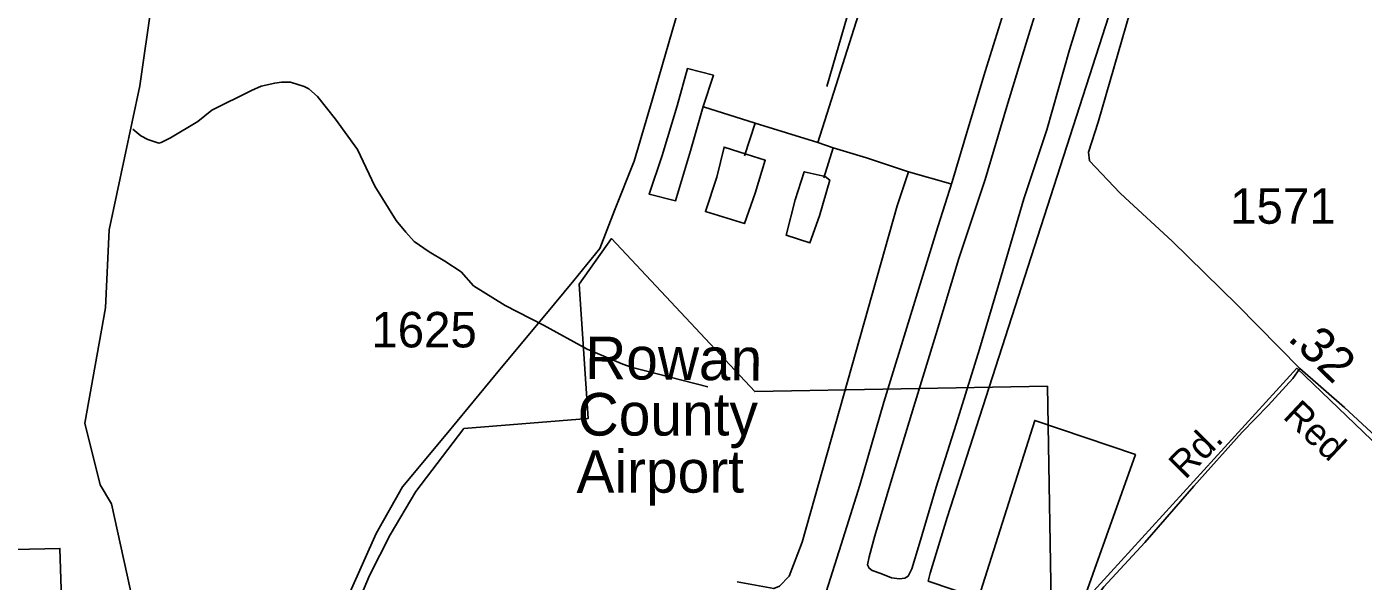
# Model space of a CAD drawing. Extents: x 1473865 to 1648260, y 639067 to 773536.
# Drawn here: x 1545209 to 1549921, y 692603 to 694557 of the extents above; entities that cross this region are included whole.
import ezdxf

# ---------------------------------------------------------------- set-up
doc = ezdxf.new("R2010")
doc.units = 0
for name, color, linetype in [('Exist Aviation Commercial or Municipal Label', 7, 'Continuous'), ('Exist Aviation Commercial or Municipal Perimeter Paved', 7, 'Continuous'), ('Exist Boundary Political City Limit New', 7, 'Continuous'), ('Exist Hydrographic Creek Single Shore', 7, 'Continuous'), ('Exist Hydrographic Misc Water Feature', 7, 'Continuous'), ('Exist Road Non-System Type 51', 7, 'Continuous'), ('Exist Road Non-System Type 51 Label', 7, 'Continuous'), ('Exist Road Secondary Mileage Hundredths English Label', 7, 'Continuous'), ('Exist Road Secondary Type 51 Attributed', 7, 'Continuous'), ('Exist Road Secondary Type 51 Label', 7, 'Continuous'), ('Exist Road Secondary Type 51 Number Label', 7, 'Continuous'), ('Map Preparation Boundary City Limit Buffer Line', 7, 'Continuous')]:
    doc.layers.add(name, color=color, linetype=linetype)

msp = doc.modelspace()

# ---------------------------------------------------------------- linework, layer by layer
at = {"layer": 'Exist Aviation Commercial or Municipal Perimeter Paved'}
for points in [[(1549286.7, 695409), (1548454.1, 692828.4), (1548394.9, 692631.3), (1548387.4, 692604)], [(1548179.8, 692689.1), (1548199.1, 692762.9), (1548262.6, 692975.9), (1548336.8, 693218.8), (1548414.9, 693471.5), (1548495.6, 693740.4), (1548588.3, 694018.9), (1548664.7, 694275.9), (1548732.4, 694498.8), (1548776.7, 694640.2)], [(1547776.4, 690720.4), (1547595.9, 690798.6), (1547511.6, 690485.6), (1547415.4, 690533.8), (1547535.9, 690919), (1547561.2, 691000.7), (1547603.8, 691148.1), (1547680, 691402.9), (1547747.9, 691623.8), (1547821.9, 691872.7), (1547902.5, 692137.6), (1547959.6, 692320.7), (1548012.8, 692517.9), (1548080.4, 692732.9), (1548146.1, 692941.9), (1548231, 693234.7), (1548421.4, 693851.8), (1548472, 694011), (1548527.2, 694196.2), (1548588.7, 694399.3), (1548658.5, 694624.2)], [(1548930.4, 694619.5), (1548886, 694476.1), (1548805.3, 694193.4), (1548725.1, 693950.5), (1548644.6, 693677.8), (1548568.2, 693421), (1548485.8, 693156.1), (1548416.1, 692935.2), (1548356.6, 692736.1), (1548329.2, 692646.4), (1548316.7, 692620.7), (1548305.1, 692613.7), (1548286.5, 692611.3), (1548258.5, 692615.6), (1548220.8, 692630.4), (1548190.2, 692641.4), (1548179.2, 692649.3), (1548173.4, 692661.2), (1548179.8, 692689.1)], [(1547594.4, 694276.3), (1547630.2, 694385.8), (1547538.6, 694409.5), (1547502.3, 694277.9), (1547449.4, 694102.7), (1547403.2, 693967.4), (1547496.8, 693943.9), (1547549.8, 694119.1), (1547594.4, 694276.3)], [(1547745.6, 694107.6), (1547667.9, 694132.9), (1547642.2, 694027.4), (1547602.1, 693905.9), (1547739.5, 693863.5), (1547777.3, 693971), (1547813.2, 694086.4), (1547745.6, 694107.6)], [(1548024.4, 694028.7), (1548040.1, 694016.6), (1548004, 693891), (1547970.4, 693795.5), (1547886.7, 693823), (1547918.9, 693946.6), (1547950.5, 694046), (1548024.4, 694028.7)], [(1548387.4, 692604), (1548564.6, 692544.1), (1548763.2, 693170), (1549118.2, 693049.7), (1548817.3, 692207), (1548817.3, 692309.3), (1548781.2, 692309.3), (1548703, 691966.3), (1548697, 691563), (1548666.9, 690997.2), (1548137.4, 691051.4), (1548221.6, 690919), (1548480.4, 690931), (1548456.3, 690822.7), (1548221.6, 690852.8), (1548059.2, 691051.4), (1547974.9, 691051.4), (1547872.6, 690720.4), (1548023.1, 690467.6), (1548648.9, 690268.9), (1548588.7, 690112.5), (1547974.9, 690353.2), (1547776.4, 690720.4)]]:
    msp.add_lwpolyline(points, dxfattribs=at)
at = {"layer": 'Exist Boundary Political City Limit New'}
msp.add_lwpolyline([(1550303.1, 692762.7), (1549687.6, 693353.7), (1548922.2, 692515.4), (1548822.9, 692391.2), (1548807.9, 693290), (1547776, 693271.3), (1547271.4, 693810.6), (1547156.9, 693650.1), (1547188.5, 693176.6), (1546750.5, 693141.1), (1546581.2, 692919.3), (1546490, 692766.8), (1546417.6, 692623.3), (1546344.5, 692451.1), (1546292.9, 692292.6), (1546220.5, 691956), (1546205.5, 691700.6), (1545361.1, 691645.4), (1545326, 692719.1), (1544737.1, 692705.2)], dxfattribs=at)
at = {"layer": 'Exist Hydrographic Creek Single Shore'}
msp.add_lwpolyline([(1546704.6, 689412.2), (1546715.6, 690114.4), (1546602.6, 690339.9), (1546492.6, 690726.2), (1546402.5, 690869.1), (1546287.6, 690986.3), (1546191.5, 691214.8), (1546143.6, 691356.9), (1545914.6, 691666.8), (1545778.6, 691978.1), (1545699.6, 692304.7), (1545594.5, 692480.7), (1545508.6, 692876.4), (1545468.6, 692942.9), (1545413.6, 693160.6), (1545486.6, 693566.1), (1545499.6, 693841.7), (1545607.6, 694348.2), (1545691.6, 694930.8)], dxfattribs=at)
at = {"layer": 'Exist Hydrographic Misc Water Feature'}
msp.add_lwpolyline([(1545582.7, 694195.5), (1545611.9, 694172.1), (1545635.6, 694159.6), (1545675.4, 694146.8), (1545683.4, 694148.7), (1545715.8, 694166), (1545812, 694223.4), (1545861.7, 694263), (1546001.1, 694332.1), (1546035.4, 694347.4), (1546083.6, 694358.4), (1546107.7, 694362), (1546139.7, 694361.3), (1546187.3, 694346.3), (1546203.2, 694338), (1546234.7, 694311.4), (1546297.8, 694231), (1546375.1, 694124.6), (1546436.6, 693995.4), (1546512.2, 693874), (1546545.5, 693833.3), (1546574.9, 693800.7), (1546628.2, 693763.7), (1546683.6, 693730.6), (1546740.4, 693693.1), (1546783.8, 693644.5), (1546896.5, 693574.3), (1547031.2, 693505.6), (1547185.6, 693420.5), (1547310.6, 693368), (1547340.5, 693357.4), (1547611.1, 693287.9)], dxfattribs=at)
at = {"layer": 'Exist Road Non-System Type 51'}
for p, q in [((1547777.1, 694217.2), (1547595.5, 694275.1)), ((1547777.1, 694217.2), (1547739.9, 694101.5)), ((1547998.4, 694148.9), (1547777.1, 694217.2)), ((1548052.2, 694130.2), (1547998.4, 694148.9)), ((1548052.2, 694130.2), (1548019.1, 694024.6)), ((1548466.9, 694003.9), (1548317.5, 694045.6))]:
    msp.add_line(p, q, dxfattribs=at)
for points in [[(1548401.8, 695121.2), (1548363.8, 695119.6), (1548309.4, 695080.1), (1548262.5, 694998.6), (1548249.8, 694955.3), (1548208.7, 694815), (1548142.2, 694600.6), (1547998.4, 694148.9)], [(1549082.4, 693953.6), (1549062.7, 693971.7), (1548955.8, 694084.9), (1548952.2, 694115), (1548987.1, 694220.8), (1549169.2, 694851.2), (1549165.4, 694873.3), (1549131.7, 694899.6), (1548994.2, 694945), (1548655, 695046.5), (1548555.5, 695081.5)], [(1548317.5, 694045.6), (1548169.8, 694095), (1548052.2, 694130.2)], [(1547713.4, 692600.8), (1547843.2, 692577.6), (1547863.1, 692585.4), (1547897.5, 692621.1), (1547942.7, 692740.7), (1548278.2, 693925.9), (1548317.5, 694045.6)], [(1548803.4, 689775.6), (1548797.9, 689954.7), (1548754.5, 691120.6), (1548745.5, 691352.6), (1548746.4, 691949), (1548768.6, 692089.7), (1548795.9, 692221.6), (1548845, 692345.1), (1548918.1, 692470.5), (1549007.3, 692583.5), (1549150.9, 692740.1), (1549323.5, 692937.9), (1549494.4, 693127.9), (1549586.6, 693222.9), (1549673.4, 693317.9), (1549697.8, 693353.1)]]:
    msp.add_lwpolyline(points, dxfattribs=at)
at = {"layer": 'Exist Road Secondary Type 51 Attributed'}
for points in [[(1548205.5, 694950), (1548030.5, 694345.9)], [(1546235.9, 690781.3), (1546240.2, 690902.6), (1546234.8, 690994.9), (1546202.2, 691198.4), (1546165.1, 691530.9), (1546154.9, 691746.2), (1546185.6, 691951.2), (1546226.6, 692135.7), (1546267.5, 692330.5), (1546349.5, 692566.2), (1546441.7, 692771.3), (1546533.8, 692935.3), (1546687.5, 693119.8), (1546882.1, 693355.6), (1547035.7, 693540.1), (1547138.2, 693663.1), (1547230.3, 693775.8), (1547281.6, 693909.1), (1547351.1, 694083.3), (1547414.7, 694298.6), (1547588.8, 694903.4)], [(1549697.8, 693353.1), (1549477, 693577.3), (1549247.2, 693801.7), (1549082.4, 693953.6)], [(1549697.8, 693353.1), (1549855.5, 693215.1), (1549996.3, 693085.6), (1550164.7, 692923.9), (1550570.8, 692519.3), (1550662, 692440.4), (1550681.8, 692412.2), (1550842.3, 692262.5), (1550959.2, 692147.3), (1551207, 691902.6), (1551337.8, 691779.1), (1551459.8, 691676.2)]]:
    msp.add_lwpolyline(points, dxfattribs=at)
at = {"layer": 'Map Preparation Boundary City Limit Buffer Line'}
msp.add_lwpolyline([(1550303.1, 692762.7), (1549687.6, 693353.7), (1548922.2, 692515.4), (1548822.9, 692391.2), (1548807.9, 693290), (1547776, 693271.3), (1547271.4, 693810.6), (1547156.9, 693650.1), (1547188.5, 693176.6), (1546750.5, 693141.1), (1546581.2, 692919.3), (1546490, 692766.8), (1546417.6, 692623.3), (1546344.5, 692451.1), (1546292.9, 692292.6), (1546220.5, 691956), (1546205.5, 691700.6), (1545361.1, 691645.4), (1545326, 692719.1), (1544737.1, 692705.2)], dxfattribs=at)

# ---------------------------------------------------------------- texts
at = {"layer": 'Exist Aviation Commercial or Municipal Label'}
for s, rotation, p in [('Rowan', 359.4978, (1547177.4, 693315.7)), ('County', 0.0441, (1547151.6, 693116.4)), ('Airport', 0.1003, (1547147.5, 692914.7))]:
    msp.add_text(s, height=150, rotation=rotation, dxfattribs=at).set_placement(p)
at = {"layer": 'Exist Road Non-System Type 51 Label'}
msp.add_text('Rd.', height=95, rotation=45.2978, dxfattribs=at).set_placement((1549294, 692959.3))
at = {"layer": 'Exist Road Secondary Mileage Hundredths English Label'}
msp.add_text('.32', height=125, rotation=315.8056, dxfattribs=at).set_placement((1549651.5, 693456.1))
at = {"layer": 'Exist Road Secondary Type 51 Label'}
msp.add_text('Red', height=95, rotation=316.8052, dxfattribs=at).set_placement((1549634.6, 693180))
at = {"layer": 'Exist Road Secondary Type 51 Number Label'}
for s, p in [('1571', (1549452.2, 693862.8)), ('1625', (1546424.2, 693427.1))]:
    msp.add_text(s, height=125, dxfattribs=at).set_placement(p)

doc.saveas('drawing.dxf')
